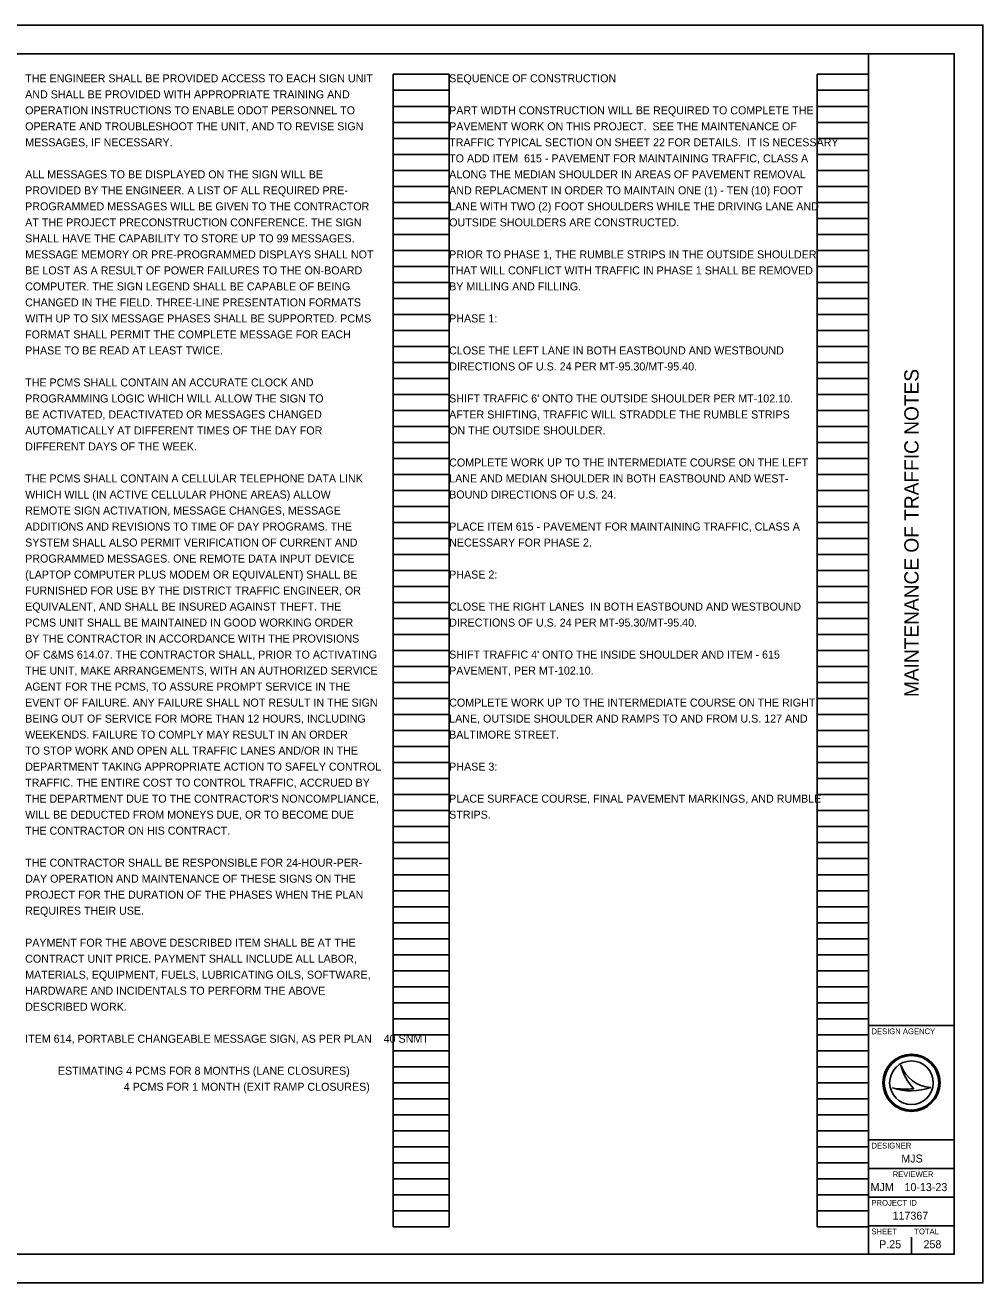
# Model space of a CAD drawing. Extents: x 0.1 to 34.1, y -1.1 to 20.9.
# Drawn here: x 17.38 to 34.14, y -1.12 to 20.88 of the extents above; entities that cross this region are included whole.
import ezdxf

# ---------------------------------------------------------------- set-up
doc = ezdxf.new("R2010")
doc.units = 0
for name, color, linetype in [('SH_Border', 7, 'Continuous'), ('SH_Cut_Line', 7, 'Continuous'), ('SH_Data', 7, 'Continuous'), ('SH_Text', 7, 'Continuous')]:
    doc.layers.add(name, color=color, linetype=linetype)

msp = doc.modelspace()

# ---------------------------------------------------------------- linework, layer by layer
at = {"layer": 'SH_Border'}
for p, q in [((32.143, -0.62), (32.143, 20.38)), ((32.143, 3.38), (33.643, 3.38)), ((32.143, 1.38), (33.643, 1.38)), ((32.143, 0.88), (33.643, 0.88)), ((32.143, 0.38), (33.643, 0.38)), ((32.143, -0.12), (33.643, -0.12))]:
    msp.add_line(p, q, dxfattribs=at)
msp.add_lwpolyline([(1.643, 20.38), (33.643, 20.38), (33.643, -0.62), (1.643, -0.62)], close=True, dxfattribs=at)
at = {"layer": 'SH_Cut_Line'}
msp.add_lwpolyline([(0.143, -1.12), (34.143, -1.12), (34.143, 20.88), (0.143, 20.88)], close=True, dxfattribs=at)
at = {"layer": 'SH_Data'}
for p, q in [((23.823, -0.14), (23.823, 20.02)), ((23.823, 20.02), (24.803, 20.02)), ((24.803, -0.14), (24.803, 20.02)), ((31.243, -0.14), (31.243, 20.02)), ((31.243, 20.02), (32.143, 20.02)), ((32.143, -0.14), (32.143, 20.02)), ((23.823, 19.74), (24.803, 19.74)), ((31.243, 19.74), (32.143, 19.74)), ((23.823, 19.46), (24.803, 19.46)), ((31.243, 19.46), (32.143, 19.46)), ((23.823, 19.18), (24.803, 19.18)), ((31.243, 19.18), (32.143, 19.18)), ((23.823, 18.9), (24.803, 18.9)), ((31.243, 18.9), (32.143, 18.9)), ((23.823, 18.62), (24.803, 18.62)), ((31.243, 18.62), (32.143, 18.62)), ((23.823, 18.34), (24.803, 18.34)), ((31.243, 18.34), (32.143, 18.34)), ((23.823, 18.06), (24.803, 18.06)), ((31.243, 18.06), (32.143, 18.06)), ((23.823, 17.78), (24.803, 17.78)), ((31.243, 17.78), (32.143, 17.78)), ((23.823, 17.5), (24.803, 17.5)), ((31.243, 17.5), (32.143, 17.5)), ((23.823, 17.22), (24.803, 17.22)), ((31.243, 17.22), (32.143, 17.22)), ((23.823, 16.94), (24.803, 16.94)), ((31.243, 16.94), (32.143, 16.94)), ((23.823, 16.66), (24.803, 16.66)), ((31.243, 16.66), (32.143, 16.66)), ((23.823, 16.38), (24.803, 16.38)), ((31.243, 16.38), (32.143, 16.38)), ((23.823, 16.1), (24.803, 16.1)), ((31.243, 16.1), (32.143, 16.1)), ((23.823, 15.82), (24.803, 15.82)), ((31.243, 15.82), (32.143, 15.82)), ((23.823, 15.54), (24.803, 15.54)), ((31.243, 15.54), (32.143, 15.54)), ((23.823, 15.26), (24.803, 15.26)), ((31.243, 15.26), (32.143, 15.26)), ((23.823, 14.98), (24.803, 14.98)), ((31.243, 14.98), (32.143, 14.98)), ((23.823, 14.7), (24.803, 14.7)), ((31.243, 14.7), (32.143, 14.7)), ((23.823, 14.42), (24.803, 14.42)), ((31.243, 14.42), (32.143, 14.42)), ((23.823, 14.14), (24.803, 14.14)), ((31.243, 14.14), (32.143, 14.14)), ((23.823, 13.86), (24.803, 13.86)), ((31.243, 13.86), (32.143, 13.86)), ((23.823, 13.58), (24.803, 13.58)), ((31.243, 13.58), (32.143, 13.58)), ((23.823, 13.3), (24.803, 13.3)), ((31.243, 13.3), (32.143, 13.3)), ((23.823, 13.02), (24.803, 13.02)), ((31.243, 13.02), (32.143, 13.02)), ((23.823, 12.74), (24.803, 12.74)), ((31.243, 12.74), (32.143, 12.74)), ((23.823, 12.46), (24.803, 12.46)), ((31.243, 12.46), (32.143, 12.46)), ((23.823, 12.18), (24.803, 12.18)), ((31.243, 12.18), (32.143, 12.18)), ((23.823, 11.9), (24.803, 11.9)), ((31.243, 11.9), (32.143, 11.9)), ((23.823, 11.62), (24.803, 11.62)), ((31.243, 11.62), (32.143, 11.62)), ((23.823, 11.34), (24.803, 11.34)), ((31.243, 11.34), (32.143, 11.34)), ((23.823, 11.06), (24.803, 11.06)), ((31.243, 11.06), (32.143, 11.06)), ((23.823, 10.78), (24.803, 10.78)), ((31.243, 10.78), (32.143, 10.78)), ((23.823, 10.5), (24.803, 10.5)), ((31.243, 10.5), (32.143, 10.5)), ((23.823, 10.22), (24.803, 10.22)), ((31.243, 10.22), (32.143, 10.22)), ((23.823, 9.94), (24.803, 9.94)), ((31.243, 9.94), (32.143, 9.94)), ((23.823, 9.66), (24.803, 9.66)), ((31.243, 9.66), (32.143, 9.66)), ((23.823, 9.38), (24.803, 9.38)), ((31.243, 9.38), (32.143, 9.38)), ((23.823, 9.1), (24.803, 9.1)), ((31.243, 9.1), (32.143, 9.1)), ((23.823, 8.82), (24.803, 8.82)), ((31.243, 8.82), (32.143, 8.82)), ((23.823, 8.54), (24.803, 8.54)), ((31.243, 8.54), (32.143, 8.54)), ((23.823, 8.26), (24.803, 8.26)), ((31.243, 8.26), (32.143, 8.26)), ((23.823, 7.98), (24.803, 7.98)), ((31.243, 7.98), (32.143, 7.98)), ((23.823, 7.7), (24.803, 7.7)), ((31.243, 7.7), (32.143, 7.7)), ((23.823, 7.42), (24.803, 7.42)), ((31.243, 7.42), (32.143, 7.42)), ((23.823, 7.14), (24.803, 7.14)), ((31.243, 7.14), (32.143, 7.14)), ((23.823, 6.86), (24.803, 6.86)), ((31.243, 6.86), (32.143, 6.86)), ((23.823, 6.58), (24.803, 6.58)), ((31.243, 6.58), (32.143, 6.58)), ((23.823, 6.3), (24.803, 6.3)), ((31.243, 6.3), (32.143, 6.3)), ((23.823, 6.02), (24.803, 6.02)), ((31.243, 6.02), (32.143, 6.02)), ((23.823, 5.74), (24.803, 5.74)), ((31.243, 5.74), (32.143, 5.74)), ((23.823, 5.46), (24.803, 5.46)), ((31.243, 5.46), (32.143, 5.46)), ((23.823, 5.18), (24.803, 5.18)), ((31.243, 5.18), (32.143, 5.18)), ((23.823, 4.9), (24.803, 4.9)), ((31.243, 4.9), (32.143, 4.9)), ((23.823, 4.62), (24.803, 4.62)), ((31.243, 4.62), (32.143, 4.62)), ((23.823, 4.34), (24.803, 4.34)), ((31.243, 4.34), (32.143, 4.34)), ((23.823, 4.06), (24.803, 4.06)), ((31.243, 4.06), (32.143, 4.06)), ((23.823, 3.78), (24.803, 3.78)), ((31.243, 3.78), (32.143, 3.78)), ((23.823, 3.5), (24.803, 3.5)), ((31.243, 3.5), (32.143, 3.5)), ((23.823, 3.22), (24.803, 3.22)), ((31.243, 3.22), (32.143, 3.22)), ((23.823, 2.94), (24.803, 2.94)), ((31.243, 2.94), (32.143, 2.94)), ((23.823, 2.66), (24.803, 2.66)), ((31.243, 2.66), (32.143, 2.66)), ((32.71, 2.69), (32.71, 2.69)), ((23.823, 2.38), (24.803, 2.38)), ((31.243, 2.38), (32.143, 2.38)), ((32.56, 2.29), (32.56, 2.29)), ((32.893, 2.38), (32.893, 2.38)), ((33.23, 2.299), (33.23, 2.299)), ((23.823, 2.1), (24.803, 2.1)), ((31.243, 2.1), (32.143, 2.1)), ((23.823, 1.82), (24.803, 1.82)), ((31.243, 1.82), (32.143, 1.82)), ((23.823, 1.54), (24.803, 1.54)), ((31.243, 1.54), (32.143, 1.54)), ((23.823, 1.26), (24.803, 1.26)), ((31.243, 1.26), (32.143, 1.26)), ((23.823, 0.98), (24.803, 0.98)), ((31.243, 0.98), (32.143, 0.98)), ((23.823, 0.7), (24.803, 0.7)), ((31.243, 0.7), (32.143, 0.7)), ((23.823, 0.42), (24.803, 0.42)), ((31.243, 0.42), (32.143, 0.42)), ((23.823, 0.14), (24.803, 0.14)), ((31.243, 0.14), (32.143, 0.14)), ((23.823, -0.14), (24.803, -0.14)), ((31.243, -0.14), (32.143, -0.14)), ((32.893, -0.62), (32.893, -0.32)), ((32.518, -0.445), (32.518, -0.445))]:
    msp.add_line(p, q, dxfattribs=at)
for radius in [0.5, 0.477, 0.477, 0.382]:
    msp.add_circle((32.893, 2.38), radius, dxfattribs=at)
for centre, radius, start, end in [((33.258, 2.878), 0.58, 198.9257, 198.9319), ((33.489, 2.85), 0.796, 191.6379, 191.6421), ((33.258, 2.878), 0.58, 198.9319, 267.1657), ((33.489, 2.85), 0.796, 191.6421, 226.0947), ((32.882, 3.25), 1.013, 251.4576, 290.0832), ((32.79, 3.534), 1.266, 259.4964, 259.4995), ((32.882, 3.25), 1.013, 251.4527, 251.4576), ((32.79, 3.534), 1.266, 259.4995, 276.6672)]:
    msp.add_arc(centre, radius, start, end, dxfattribs=at)

# ---------------------------------------------------------------- texts
msp.add_text('MAINTENANCE OF TRAFFIC NOTES', height=0.25, rotation=90, dxfattribs=at).set_placement((33.018, 9.127))
for s, height, p in [('DESIGN AGENCY', 0.1, (32.193, 3.23)), ('DESIGNER', 0.1, (32.193, 1.23)), ('MJS', 0.14, (32.716, 0.985)), ('REVIEWER', 0.1, (32.564, 0.73)), ('MJM', 0.14, (32.178, 0.485)), ('10-13-23', 0.14, (32.771, 0.485)), ('PROJECT ID', 0.1, (32.193, 0.23)), ('117367', 0.14, (32.562, -0.015)), ('SHEET', 0.1, (32.193, -0.27)), ('TOTAL', 0.1, (32.943, -0.27)), ('P.25', 0.14, (32.327, -0.515)), ('258', 0.14, (33.104, -0.515))]:
    msp.add_text(s, height=height, dxfattribs=at).set_placement(p)
at = {"layer": 'SH_Text'}
for s, p in [('THE ENGINEER SHALL BE PROVIDED ACCESS TO EACH SIGN UNIT', (17.383, 19.88)), ('SEQUENCE OF CONSTRUCTION', (24.803, 19.88)), ('AND SHALL BE PROVIDED WITH APPROPRIATE TRAINING AND', (17.383, 19.6)), ('OPERATION INSTRUCTIONS TO ENABLE ODOT PERSONNEL TO', (17.383, 19.32)), ('PART WIDTH CONSTRUCTION WILL BE REQUIRED TO COMPLETE THE', (24.803, 19.32)), ('OPERATE AND TROUBLESHOOT THE UNIT, AND TO REVISE SIGN', (17.383, 19.04)), ('PAVEMENT WORK ON THIS PROJECT.  SEE THE MAINTENANCE OF ', (24.803, 19.04)), ('MESSAGES, IF NECESSARY.', (17.383, 18.76)), ('TRAFFIC TYPICAL SECTION ON SHEET 22 FOR DETAILS.  IT IS NECESSARY ', (24.803, 18.76)), ('TO ADD ITEM  615 - PAVEMENT FOR MAINTAINING TRAFFIC, CLASS A ', (24.803, 18.48)), ('ALL MESSAGES TO BE DISPLAYED ON THE SIGN WILL BE', (17.383, 18.2)), ('ALONG THE MEDIAN SHOULDER IN AREAS OF PAVEMENT REMOVAL ', (24.803, 18.2)), ('PROVIDED BY THE ENGINEER. A LIST OF ALL REQUIRED PRE-', (17.383, 17.92)), ('AND REPLACMENT IN ORDER TO MAINTAIN ONE (1) - TEN (10) FOOT ', (24.803, 17.92)), ('PROGRAMMED MESSAGES WILL BE GIVEN TO THE CONTRACTOR', (17.383, 17.64)), ('LANE WITH TWO (2) FOOT SHOULDERS WHILE THE DRIVING LANE AND ', (24.803, 17.64)), ('AT THE PROJECT PRECONSTRUCTION CONFERENCE. THE SIGN', (17.383, 17.36)), ('OUTSIDE SHOULDERS ARE CONSTRUCTED.', (24.803, 17.36)), ('SHALL HAVE THE CAPABILITY TO STORE UP TO 99 MESSAGES.', (17.383, 17.08)), ('MESSAGE MEMORY OR PRE-PROGRAMMED DISPLAYS SHALL NOT', (17.383, 16.8)), ('PRIOR TO PHASE 1, THE RUMBLE STRIPS IN THE OUTSIDE SHOULDER', (24.803, 16.8)), ('BE LOST AS A RESULT OF POWER FAILURES TO THE ON-BOARD', (17.383, 16.52)), ('THAT WILL CONFLICT WITH TRAFFIC IN PHASE 1 SHALL BE REMOVED', (24.803, 16.52)), ('COMPUTER. THE SIGN LEGEND SHALL BE CAPABLE OF BEING', (17.383, 16.24)), ('BY MILLING AND FILLING.', (24.803, 16.24)), ('CHANGED IN THE FIELD. THREE-LINE PRESENTATION FORMATS', (17.383, 15.96)), ('WITH UP TO SIX MESSAGE PHASES SHALL BE SUPPORTED. PCMS', (17.383, 15.68)), ('PHASE 1:', (24.803, 15.68)), ('FORMAT SHALL PERMIT THE COMPLETE MESSAGE FOR EACH', (17.383, 15.4)), ('PHASE TO BE READ AT LEAST TWICE.', (17.383, 15.12)), ('CLOSE THE LEFT LANE IN BOTH EASTBOUND AND WESTBOUND', (24.803, 15.12)), ('DIRECTIONS OF U.S. 24 PER MT-95.30/MT-95.40.', (24.803, 14.84)), ('THE PCMS SHALL CONTAIN AN ACCURATE CLOCK AND', (17.383, 14.56)), ('PROGRAMMING LOGIC WHICH WILL ALLOW THE SIGN TO', (17.383, 14.28)), ("SHIFT TRAFFIC 6' ONTO THE OUTSIDE SHOULDER PER MT-102.10.", (24.803, 14.28)), ('BE ACTIVATED, DEACTIVATED OR MESSAGES CHANGED', (17.383, 14)), ('AFTER SHIFTING, TRAFFIC WILL STRADDLE THE RUMBLE STRIPS', (24.803, 14)), ('AUTOMATICALLY AT DIFFERENT TIMES OF THE DAY FOR', (17.383, 13.72)), ('ON THE OUTSIDE SHOULDER.', (24.803, 13.72)), ('DIFFERENT DAYS OF THE WEEK.', (17.383, 13.44)), ('COMPLETE WORK UP TO THE INTERMEDIATE COURSE ON THE LEFT ', (24.803, 13.16)), ('THE PCMS SHALL CONTAIN A CELLULAR TELEPHONE DATA LINK', (17.383, 12.88)), ('LANE AND MEDIAN SHOULDER IN BOTH EASTBOUND AND WEST-', (24.803, 12.88)), ('WHICH WILL (IN ACTIVE CELLULAR PHONE AREAS) ALLOW', (17.383, 12.6)), ('BOUND DIRECTIONS OF U.S. 24.', (24.803, 12.6)), ('REMOTE SIGN ACTIVATION, MESSAGE CHANGES, MESSAGE', (17.383, 12.32)), ('ADDITIONS AND REVISIONS TO TIME OF DAY PROGRAMS. THE', (17.383, 12.04)), ('PLACE ITEM 615 - PAVEMENT FOR MAINTAINING TRAFFIC, CLASS A ', (24.803, 12.04)), ('SYSTEM SHALL ALSO PERMIT VERIFICATION OF CURRENT AND', (17.383, 11.76)), ('NECESSARY FOR PHASE 2. ', (24.803, 11.76)), ('PROGRAMMED MESSAGES. ONE REMOTE DATA INPUT DEVICE', (17.383, 11.48)), ('(LAPTOP COMPUTER PLUS MODEM OR EQUIVALENT) SHALL BE', (17.383, 11.2)), ('PHASE 2:', (24.803, 11.2)), ('FURNISHED FOR USE BY THE DISTRICT TRAFFIC ENGINEER, OR', (17.383, 10.92)), ('EQUIVALENT, AND SHALL BE INSURED AGAINST THEFT. THE', (17.383, 10.64)), ('CLOSE THE RIGHT LANES  IN BOTH EASTBOUND AND WESTBOUND ', (24.803, 10.64)), ('PCMS UNIT SHALL BE MAINTAINED IN GOOD WORKING ORDER', (17.383, 10.36)), ('DIRECTIONS OF U.S. 24 PER MT-95.30/MT-95.40.', (24.803, 10.36)), ('BY THE CONTRACTOR IN ACCORDANCE WITH THE PROVISIONS', (17.383, 10.08)), ('OF C&MS 614.07. THE CONTRACTOR SHALL, PRIOR TO ACTIVATING', (17.383, 9.8)), ("SHIFT TRAFFIC 4' ONTO THE INSIDE SHOULDER AND ITEM - 615", (24.803, 9.8)), ('THE UNIT, MAKE ARRANGEMENTS, WITH AN AUTHORIZED SERVICE', (17.383, 9.52)), ('PAVEMENT, PER MT-102.10.', (24.803, 9.52)), ('AGENT FOR THE PCMS, TO ASSURE PROMPT SERVICE IN THE', (17.383, 9.24)), ('EVENT OF FAILURE. ANY FAILURE SHALL NOT RESULT IN THE SIGN', (17.383, 8.96)), ('COMPLETE WORK UP TO THE INTERMEDIATE COURSE ON THE RIGHT ', (24.803, 8.96)), ('BEING OUT OF SERVICE FOR MORE THAN 12 HOURS, INCLUDING', (17.383, 8.68)), ('LANE, OUTSIDE SHOULDER AND RAMPS TO AND FROM U.S. 127 AND ', (24.803, 8.68)), ('WEEKENDS. FAILURE TO COMPLY MAY RESULT IN AN ORDER', (17.383, 8.4)), ('BALTIMORE STREET.', (24.803, 8.4)), ('TO STOP WORK AND OPEN ALL TRAFFIC LANES AND/OR IN THE', (17.383, 8.12)), ('DEPARTMENT TAKING APPROPRIATE ACTION TO SAFELY CONTROL', (17.383, 7.84)), ('PHASE 3:', (24.803, 7.84)), ('TRAFFIC. THE ENTIRE COST TO CONTROL TRAFFIC, ACCRUED BY', (17.383, 7.56)), ("THE DEPARTMENT DUE TO THE CONTRACTOR'S NONCOMPLIANCE,", (17.383, 7.28)), ('PLACE SURFACE COURSE, FINAL PAVEMENT MARKINGS, AND RUMBLE ', (24.803, 7.28)), ('WILL BE DEDUCTED FROM MONEYS DUE, OR TO BECOME DUE', (17.383, 7)), ('STRIPS.', (24.803, 7)), ('THE CONTRACTOR ON HIS CONTRACT.', (17.383, 6.72)), ('THE CONTRACTOR SHALL BE RESPONSIBLE FOR 24-HOUR-PER-', (17.383, 6.16)), ('DAY OPERATION AND MAINTENANCE OF THESE SIGNS ON THE', (17.383, 5.88)), ('PROJECT FOR THE DURATION OF THE PHASES WHEN THE PLAN', (17.383, 5.6)), ('REQUIRES THEIR USE.', (17.383, 5.32)), ('PAYMENT FOR THE ABOVE DESCRIBED ITEM SHALL BE AT THE', (17.383, 4.76)), ('CONTRACT UNIT PRICE. PAYMENT SHALL INCLUDE ALL LABOR,', (17.383, 4.48)), ('MATERIALS, EQUIPMENT, FUELS, LUBRICATING OILS, SOFTWARE,', (17.383, 4.2)), ('HARDWARE AND INCIDENTALS TO PERFORM THE ABOVE', (17.383, 3.92)), ('DESCRIBED WORK.', (17.383, 3.64)), ('ITEM 614, PORTABLE CHANGEABLE MESSAGE SIGN, AS PER PLAN    40 SNMT', (17.383, 3.08)), ('           ESTIMATING 4 PCMS FOR 8 MONTHS (LANE CLOSURES)', (17.383, 2.52)), ('           4 PCMS FOR 1 MONTH (EXIT RAMP CLOSURES)', (18.536, 2.24))]:
    msp.add_text(s, height=0.14, dxfattribs=at).set_placement(p)

doc.saveas('drawing.dxf')
